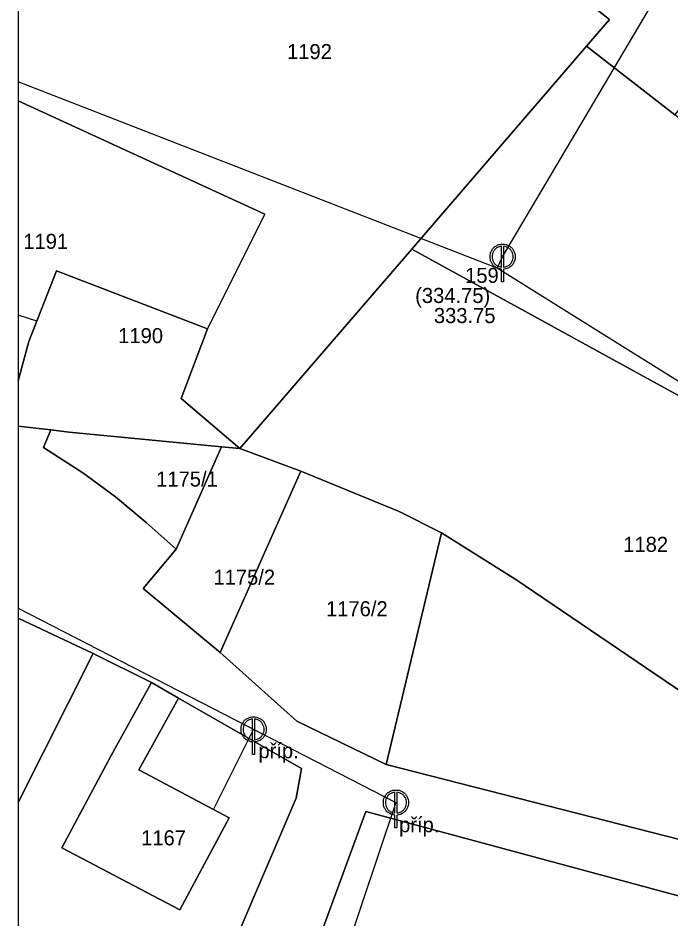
# Model space of a CAD drawing. Extents: x -559956 to -559707, y -1077221 to -1076919.
# Drawn here: x -559956.3 to -559891.3, y -1077119.6 to -1077029.9 of the extents above; entities that cross this region are included whole.
import ezdxf

# ---------------------------------------------------------------- set-up
doc = ezdxf.new("R2010")
doc.units = 0
for name, color, linetype in [('Kanalizační přípojka', 7, 'Continuous'), ('Kanalizační šachta', 7, 'Continuous'), ('Parcela-polygon', 7, 'Continuous'), ('Parcela-text', 7, 'Continuous'), ('Popis šachty', 7, 'Continuous')]:
    doc.layers.add(name, color=color, linetype=linetype)

msp = doc.modelspace()

# ---------------------------------------------------------------- linework, layer by layer
at = {"layer": 'Kanalizační přípojka'}
for p, q in [((-559908.573, -1077054.768), (-559956.266, -1077036.214)), ((-559936.808, -1077108.656), (-559932.815, -1077100.684))]:
    msp.add_line(p, q, dxfattribs=at)
for points in [[(-559908.573, -1077054.768), (-559908.02, -1077053.62), (-559878.527, -1077003.757)], [(-559855.804, -1077088.477), (-559881.332, -1077071.786), (-559908.573, -1077054.768)], [(-559954.393, -1077060.041), (-559956.266, -1077059.429)], [(-559956.266, -1077088.621), (-559918.642, -1077107.974), (-559929.055, -1077138.93), (-559927.645, -1077157.846), (-559923.52, -1077159.801)]]:
    msp.add_lwpolyline(points, dxfattribs=at)
at = {"layer": 'Kanalizační šachta'}
for points in [[(-559908.123, -1077054.655), (-559908.123, -1077052.582)], [(-559907.917, -1077052.582), (-559907.917, -1077054.655)], [(-559907.917, -1077054.868), (-559907.917, -1077056.12), (-559908.123, -1077056.12), (-559908.123, -1077054.868)], [(-559932.918, -1077101.719), (-559932.918, -1077099.646)], [(-559932.712, -1077099.646), (-559932.712, -1077101.719)], [(-559932.712, -1077101.932), (-559932.712, -1077103.184), (-559932.918, -1077103.184), (-559932.918, -1077101.932)], [(-559918.745, -1077109.009), (-559918.745, -1077106.936)], [(-559918.539, -1077106.936), (-559918.539, -1077109.009)], [(-559918.539, -1077109.222), (-559918.539, -1077110.474), (-559918.745, -1077110.474), (-559918.745, -1077109.222)]]:
    msp.add_lwpolyline(points, dxfattribs=at)
for points in [[(-559908.123, -1077054.868), (-559908.381, -1077054.85), (-559908.643, -1077054.704), (-559908.94, -1077054.54), (-559909.105, -1077054.243), (-559909.27, -1077053.945), (-559909.27, -1077053.62), (-559909.27, -1077053.293), (-559909.102, -1077052.993), (-559908.933, -1077052.692), (-559908.635, -1077052.531), (-559908.337, -1077052.37), (-559908.02, -1077052.37), (-559907.705, -1077052.37), (-559907.406, -1077052.531), (-559907.107, -1077052.692), (-559906.938, -1077052.993), (-559906.77, -1077053.293), (-559906.77, -1077053.62), (-559906.77, -1077053.945), (-559906.935, -1077054.243), (-559907.1, -1077054.54), (-559907.397, -1077054.704), (-559907.659, -1077054.85), (-559907.917, -1077054.868)], [(-559908.123, -1077052.582), (-559908.32, -1077052.599), (-559908.535, -1077052.714), (-559908.784, -1077052.849), (-559908.923, -1077053.099), (-559909.062, -1077053.349), (-559909.062, -1077053.62), (-559909.062, -1077053.891), (-559908.926, -1077054.138), (-559908.789, -1077054.384), (-559908.54, -1077054.521), (-559908.328, -1077054.641), (-559908.123, -1077054.655)], [(-559907.917, -1077054.655), (-559907.712, -1077054.641), (-559907.498, -1077054.521), (-559907.251, -1077054.384), (-559907.114, -1077054.138), (-559906.978, -1077053.891), (-559906.978, -1077053.62), (-559906.978, -1077053.349), (-559907.118, -1077053.099), (-559907.258, -1077052.849), (-559907.507, -1077052.714), (-559907.72, -1077052.599), (-559907.917, -1077052.582)], [(-559932.918, -1077101.932), (-559933.176, -1077101.914), (-559933.438, -1077101.768), (-559933.735, -1077101.604), (-559933.9, -1077101.307), (-559934.065, -1077101.009), (-559934.065, -1077100.684), (-559934.065, -1077100.357), (-559933.897, -1077100.057), (-559933.728, -1077099.756), (-559933.43, -1077099.595), (-559933.132, -1077099.434), (-559932.815, -1077099.434), (-559932.5, -1077099.434), (-559932.201, -1077099.595), (-559931.902, -1077099.756), (-559931.733, -1077100.057), (-559931.565, -1077100.357), (-559931.565, -1077100.684), (-559931.565, -1077101.009), (-559931.73, -1077101.307), (-559931.895, -1077101.604), (-559932.192, -1077101.768), (-559932.454, -1077101.914), (-559932.712, -1077101.932)], [(-559932.918, -1077099.646), (-559933.115, -1077099.663), (-559933.33, -1077099.778), (-559933.579, -1077099.913), (-559933.718, -1077100.163), (-559933.857, -1077100.413), (-559933.857, -1077100.684), (-559933.857, -1077100.955), (-559933.721, -1077101.202), (-559933.584, -1077101.448), (-559933.335, -1077101.585), (-559933.123, -1077101.705), (-559932.918, -1077101.719)], [(-559932.712, -1077101.719), (-559932.507, -1077101.705), (-559932.293, -1077101.585), (-559932.046, -1077101.448), (-559931.909, -1077101.202), (-559931.773, -1077100.955), (-559931.773, -1077100.684), (-559931.773, -1077100.413), (-559931.913, -1077100.163), (-559932.053, -1077099.913), (-559932.302, -1077099.778), (-559932.515, -1077099.663), (-559932.712, -1077099.646)], [(-559918.745, -1077109.222), (-559919.003, -1077109.204), (-559919.265, -1077109.058), (-559919.562, -1077108.894), (-559919.727, -1077108.597), (-559919.892, -1077108.299), (-559919.892, -1077107.974), (-559919.892, -1077107.647), (-559919.724, -1077107.347), (-559919.555, -1077107.046), (-559919.257, -1077106.885), (-559918.959, -1077106.724), (-559918.642, -1077106.724), (-559918.327, -1077106.724), (-559918.028, -1077106.885), (-559917.729, -1077107.046), (-559917.56, -1077107.347), (-559917.392, -1077107.647), (-559917.392, -1077107.974), (-559917.392, -1077108.299), (-559917.557, -1077108.597), (-559917.722, -1077108.894), (-559918.019, -1077109.058), (-559918.281, -1077109.204), (-559918.539, -1077109.222)], [(-559918.745, -1077106.936), (-559918.942, -1077106.953), (-559919.157, -1077107.068), (-559919.406, -1077107.203), (-559919.545, -1077107.453), (-559919.684, -1077107.703), (-559919.684, -1077107.974), (-559919.684, -1077108.245), (-559919.548, -1077108.492), (-559919.411, -1077108.738), (-559919.162, -1077108.875), (-559918.95, -1077108.995), (-559918.745, -1077109.009)], [(-559918.539, -1077109.009), (-559918.334, -1077108.995), (-559918.12, -1077108.875), (-559917.873, -1077108.738), (-559917.736, -1077108.492), (-559917.6, -1077108.245), (-559917.6, -1077107.974), (-559917.6, -1077107.703), (-559917.74, -1077107.453), (-559917.88, -1077107.203), (-559918.129, -1077107.068), (-559918.342, -1077106.953), (-559918.539, -1077106.936)]]:
    msp.add_open_spline(points, degree=3, dxfattribs=at)
at = {"layer": 'Parcela-polygon'}
for p, q in [((-559956.266, -1077016.3), (-559956.266, -1077038.099)), ((-559956.266, -1077038.099), (-559956.266, -1077065.992)), ((-559956.266, -1077065.992), (-559956.266, -1077070.49)), ((-559956.266, -1077070.49), (-559956.266, -1077089.622)), ((-559956.266, -1077089.622), (-559956.266, -1077107.97)), ((-559956.266, -1077107.97), (-559956.266, -1077124.853))]:
    msp.add_line(p, q, dxfattribs=at)
for points in [[(-559888.94, -1077008.18), (-559902.26, -1077026.17), (-559897.39, -1077030), (-559899.67, -1077032.65), (-559890.87, -1077039.51), (-559889.51, -1077037.9), (-559886.76, -1077034.59), (-559883.82, -1077031.07), (-559882.16, -1077032.46), (-559880.99, -1077030.45), (-559880.21, -1077029.16), (-559888.42, -1077024.31), (-559880.14, -1077010.46)], [(-559853.86, -1077084.2), (-559852.37, -1077082.21), (-559854.5, -1077067.83), (-559862.41, -1077061.67), (-559890.87, -1077039.51), (-559899.67, -1077032.65), (-559917.05, -1077052.87), (-559855.64, -1077086.59)], [(-559918.33, -1077079), (-559914.1, -1077081.1), (-559906.71, -1077085.76), (-559872.43, -1077109.04), (-559855.64, -1077086.59), (-559917.05, -1077052.87), (-559934.19, -1077072.71), (-559928.12, -1077074.97)], [(-559951.17, -1077071.08), (-559953.01, -1077070.87), (-559953.72, -1077072.62), (-559949.8, -1077075.14), (-559946.57, -1077077.52), (-559943.5, -1077080.07), (-559940.53, -1077082.73), (-559936, -1077072.54)], [(-559936, -1077072.54), (-559940.53, -1077082.73), (-559943.82, -1077086.65), (-559936.14, -1077093.02), (-559928.12, -1077074.97), (-559934.19, -1077072.71)], [(-559928.12, -1077074.97), (-559936.14, -1077093.02), (-559928.5, -1077099.87), (-559919.63, -1077104.19), (-559914.1, -1077081.1), (-559918.33, -1077079)], [(-559919.63, -1077104.19), (-559853.81, -1077121), (-559869.45, -1077111.31), (-559872.43, -1077109.04), (-559906.71, -1077085.76), (-559914.1, -1077081.1)], [(-559944.25, -1077104.72), (-559940.3, -1077097.56), (-559942.99, -1077096.02), (-559946.99, -1077103.27), (-559951.89, -1077112.49), (-559940.16, -1077118.64), (-559935.25, -1077109.48)], [(-559921.63, -1077108.87), (-559932.27, -1077137.8), (-559867.06, -1077160.72), (-559858.06, -1077126.03)]]:
    msp.add_lwpolyline(points, close=True, dxfattribs=at)
for points in [[(-559956.266, -1077038.099), (-559931.69, -1077049.38), (-559937.39, -1077060.79), (-559940.03, -1077067.75), (-559934.19, -1077072.71), (-559917.05, -1077052.87), (-559899.67, -1077032.65), (-559897.39, -1077030), (-559902.26, -1077026.17), (-559919.7, -1077011.48), (-559939.19, -1077016.99), (-559943.78, -1077017.51), (-559956.266, -1077016.3)], [(-559956.266, -1077065.992), (-559955.18, -1077062.06), (-559952.44, -1077055.03), (-559937.39, -1077060.79), (-559931.69, -1077049.38), (-559956.266, -1077038.099)], [(-559956.266, -1077070.49), (-559953.01, -1077070.87), (-559951.17, -1077071.08), (-559936, -1077072.54), (-559934.19, -1077072.71), (-559940.03, -1077067.75), (-559937.39, -1077060.79), (-559952.44, -1077055.03), (-559955.18, -1077062.06), (-559956.266, -1077065.992)], [(-559956.266, -1077180.273), (-559954.11, -1077184.61), (-559949.3, -1077185.88), (-559943.92, -1077169.97), (-559932.27, -1077137.8), (-559921.63, -1077108.87), (-559858.06, -1077126.03), (-559856.67, -1077126.39), (-559853.81, -1077121), (-559919.63, -1077104.19), (-559928.5, -1077099.87), (-559936.14, -1077093.02), (-559943.82, -1077086.65), (-559940.53, -1077082.73), (-559943.5, -1077080.07), (-559946.57, -1077077.52), (-559949.8, -1077075.14), (-559953.72, -1077072.62), (-559953.01, -1077070.87), (-559956.266, -1077070.49)], [(-559956.266, -1077089.622), (-559948.77, -1077093.13), (-559942.99, -1077096.02), (-559940.3, -1077097.56), (-559928.05, -1077104.59), (-559928.59, -1077107.52), (-559934.37, -1077121.11), (-559939.69, -1077134.69), (-559942.15, -1077139.11), (-559946.53, -1077149.71), (-559949.25, -1077156.3), (-559949.03, -1077156.61), (-559951.82, -1077164.21), (-559953.08, -1077167.64), (-559954.5, -1077171.52), (-559956.266, -1077175.121)], [(-559956.266, -1077107.97), (-559948.77, -1077093.13), (-559956.266, -1077089.622)], [(-559956.266, -1077124.853), (-559954.98, -1077125.71), (-559939.69, -1077134.69), (-559934.37, -1077121.11), (-559928.59, -1077107.52), (-559928.05, -1077104.59), (-559940.3, -1077097.56), (-559944.25, -1077104.72), (-559935.25, -1077109.48), (-559940.16, -1077118.64), (-559951.89, -1077112.49), (-559946.99, -1077103.27), (-559942.99, -1077096.02), (-559948.77, -1077093.13), (-559956.266, -1077107.97)]]:
    msp.add_lwpolyline(points, dxfattribs=at)

# ---------------------------------------------------------------- texts
at = {"layer": 'Parcela-text'}
for s, p in [('1192', (-559929.48, -1077033.95)), ('1191', (-559955.74, -1077052.84)), ('1190', (-559946.29, -1077062.23)), ('1175/1', (-559942.51, -1077076.51)), ('1182', (-559896.01, -1077083.01)), ('1175/2', (-559936.81, -1077086.28)), ('1176/2', (-559925.6, -1077089.42)), ('1167', (-559944.01, -1077112.23))]:
    msp.add_text(s, height=1.5, dxfattribs=at).set_placement(p)
at = {"layer": 'Popis šachty'}
for s, p in [('159', (-559911.754, -1077056.23)), ('(334.75)', (-559916.727, -1077058.23)), ('333.75', (-559914.864, -1077060.23)), ('příp.', (-559932.332, -1077103.559)), ('příp.', (-559918.33, -1077110.925))]:
    msp.add_text(s, height=1.5, dxfattribs=at).set_placement(p)

doc.saveas('drawing.dxf')
